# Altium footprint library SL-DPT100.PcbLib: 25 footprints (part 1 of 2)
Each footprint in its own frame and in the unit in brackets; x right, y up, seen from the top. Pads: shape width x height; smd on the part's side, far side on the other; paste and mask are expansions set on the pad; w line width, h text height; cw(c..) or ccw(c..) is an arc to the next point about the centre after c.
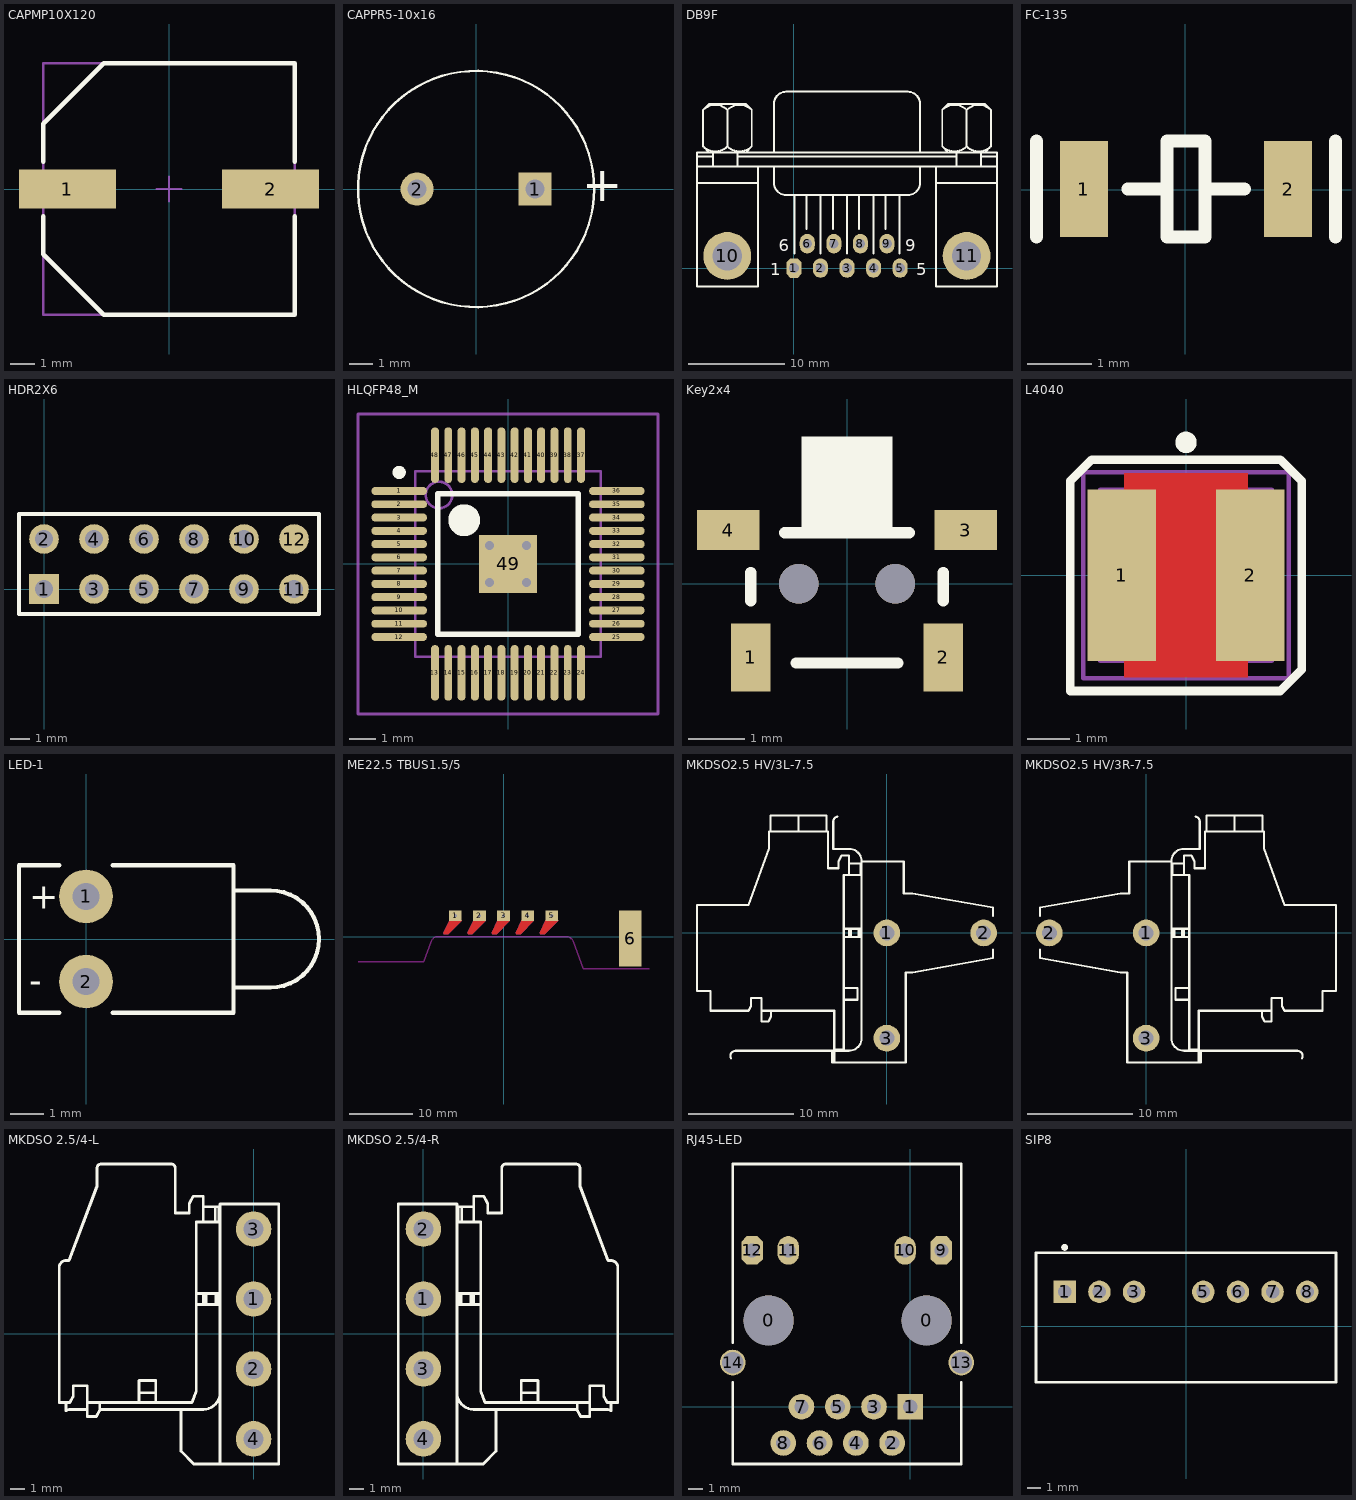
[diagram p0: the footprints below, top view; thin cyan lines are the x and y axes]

## CAPMP10X120 [mm] "Molded Capacitor, 2-Leads, Body 10mmx12mm, IPC High Density"
height 12
pads (2):
  rect 4x1.6 smd: 1(-4.2,0) 2(4.2,0)
Top Overlay:
  lines w0.2: -5.2,-1.125 -5.2,-2.7 -2.7,-5.2 5.2,-5.2 5.2,-1.125 ; -5.2,1.125 -5.2,2.7 -2.7,5.2 5.2,5.2 5.2,1.125
Mechanical 13:
  lines w0.1: -5.2,-2.7 -2.7,-5.2 5.2,-5.2 5.2,5.2 -2.7,5.2 -5.2,2.7 -5.2,-2.7
Mechanical 15:
  lines w0.1: -0.5,0 0.5,0 ; 0,-0.5 0,0.5 ; -5.2,-5.2 5.2,-5.2 5.2,5.2 -5.2,5.2 -5.2,-5.2
3D body: height 12.1, standoff 0.1, extent -4.98,-5 4.98,4.98

## CAPPR5-10x16 [mm] "Capacitor, Electrolytic, Radial; Body 10 x 16 mm (Dia.xH typ); Pin Spacing 5 mm (typ)"
height 10
pads (2):
  rect 1.4x1.4 hole 0.8: 1(2.5,0)
  round 1.4 hole 0.8: 2(-2.5,0)
Top Overlay:
  circle w0.1: c0,0 r5
  text "+" at 6.2,0.75 h1.5

## DB9F [mil]
height 62.99
pads (11):
  oct 62x80 hole 40: 1(0,0)
  oval 62x80 hole 40: 2(109.17,0) 3(218.33,0) 4(327.5,0) 5(436.67,0) 6(55,100) 7(164.17,100) 8(273.33,100) 9(382.5,100)
  round 196.67 hole 120: 10(-274.17,50) 11(710,50)
Top Overlay:
  lines w8: -398.33,350 -148.33,350 ; -398.33,416.67 835,416.67 ; -398.33,458.33 -331.67,458.33 ; -373.42,499.91 ccw(c-323.33,550) -273.25,499.91 ; -373.42,650.09 cw(c-323.33,600) -273.25,650.09 ; -348.33,475 -373.33,500 -373.33,650 -348.33,675 -198.33,675 -173.33,650 -173.33,500 -198.33,475 ; -331.67,416.67 -331.67,475 ; -273.42,499.91 ccw(c-223.33,550) -173.25,499.91 ; -273.42,650.09 cw(c-223.33,600) -173.25,650.09 ; -273.33,500 -273.33,650 ; -231.67,416.67 -231.67,475 ; -231.67,458.33 668.33,458.33 ; -148.33,416.67 -148.33,-75 -398.33,-75 -398.33,475 835,475 835,-75 585,-75 585,416.67 ; -81.67,416.67 -81.67,350 ccw(c-31.67,350) -31.67,300 468.33,300 ccw(c468.33,350) 518.33,350 518.33,416.67 ; -81.67,475 -81.67,675 cw(c-31.67,675) -31.67,725 468.33,725 cw(c468.33,675) 518.33,675 518.33,475 ; 1.67,60.4 1.67,300 ; 51.67,160 51.67,300 ; 110,60.4 110,300 ; 160,160.4 160,300 ; 218.33,60.4 218.33,300 ; 268.33,160 268.33,300 ; 326.67,60.4 326.67,300 ; 376.67,160 376.67,300 ; 435,60.4 435,300 ; 585,350 835,350 ; 609.91,499.91 ccw(c660,550) 710.09,499.91 ; 609.91,650.09 cw(c660,600) 710.09,650.09 ; 635,475 610,500 610,650 635,675 785,675 810,650 810,500 785,475 ; 668.33,416.67 668.33,475 ; 709.91,499.91 ccw(c760,550) 810.09,499.91 ; 709.91,650.09 cw(c760,600) 810.09,650.09 ; 710,500 710,650 ; 768.33,416.67 768.33,475 ; 768.33,458.33 835,458.33
  text "6" at -61.67,70 h50
  text "1" at -96.67,-30 h50
  text "5" at 503.33,-30 h50
  text "9" at 458.33,70 h50

## FC-135 [mm]
height 1.2
pads (2):
  rect 0.75x1.5 smd: 1(-1.587,0.011) 2(1.613,0.011)
Top Overlay:
  lines w0.203: -2.329,-0.739 -2.329,0.761 ; -0.9,0.011 -0.287,0.011 ; 0.413,0.011 0.93,0.011 ; 2.355,-0.739 2.355,0.761 ; -0.287,-0.739 -0.287,0.761 0.313,0.761 0.313,-0.739 -0.287,-0.739

## HDR2X6 [mm] "Connector; Header; 6x2 Position"
height 1.75
pads (12):
  rect 1.5x1.5 hole 0.9: 1(0,0)
  round 1.5 hole 0.9: 2(0,2.54) 3(2.54,0) 4(2.54,2.54) 5(5.08,0) 6(5.08,2.54) 7(7.62,0) 8(7.62,2.54) 9(10.16,0) 10(10.16,2.54) 11(12.7,0)
  round 1.5 smd: 12(12.7,2.54)
Top Overlay:
  lines w0.2: -1.27,-1.27 -1.27,3.81 13.97,3.81 13.97,-1.27 -1.27,-1.27

## HLQFP48_M [mm] "48-Pin Thin Quad Flat Pack 0.5 mm Pitch, IPC Low Density"
height 1.6
pads (49):
  oval 2.1x0.3 smd: 1(-4.1,2.75) 2(-4.1,2.25) 3(-4.1,1.75) 4(-4.1,1.25) 5(-4.1,0.75) 6(-4.1,0.25) 7(-4.1,-0.25) 8(-4.1,-0.75) 9(-4.1,-1.25) 10(-4.1,-1.75) 11(-4.1,-2.25) 12(-4.1,-2.75) 25(4.1,-2.75) 26(4.1,-2.25) 27(4.1,-1.75) 28(4.1,-1.25) 29(4.1,-0.75) 30(4.1,-0.25) 31(4.1,0.25) 32(4.1,0.75) 33(4.1,1.25) 34(4.1,1.75) 35(4.1,2.25) 36(4.1,2.75)
  oval 0.3x2.1 smd: 13(-2.75,-4.1) 14(-2.25,-4.1) 15(-1.75,-4.1) 16(-1.25,-4.1) 17(-0.75,-4.1) 18(-0.25,-4.1) 19(0.25,-4.1) 20(0.75,-4.1) 21(1.25,-4.1) 22(1.75,-4.1) 23(2.25,-4.1) 24(2.75,-4.1) 37(2.75,4.1) 38(2.25,4.1) 39(1.75,4.1) 40(1.25,4.1) 41(0.75,4.1) 42(0.25,4.1) 43(-0.25,4.1) 44(-0.75,4.1) 45(-1.25,4.1) 46(-1.75,4.1) 47(-2.25,4.1) 48(-2.75,4.1)
  rect 2.2x2.2 smd: 49(0,0)
via -0.7,0.7 diameter 0.66 hole 0.33
via 0.7,0.7 diameter 0.66 hole 0.33
via 0.7,-0.7 diameter 0.66 hole 0.33
via -0.7,-0.7 diameter 0.66 hole 0.33
Top Overlay:
  circle w0.25: c-4.1,3.45 r0.125
  circle w0.6: c-1.65,1.65 r0.3
  lines w0.2: -2.65,-2.65 -2.65,2.65 2.65,2.65 2.65,-2.65 -2.65,-2.65
Mechanical 13:
  circle w0.1: c-2.6,2.6 r0.5
  lines w0.1: -3.5,-3.5 -3.5,3.5 3.5,3.5 3.5,-3.5 -3.5,-3.5
Mechanical 15:
  lines w0.1: -0.5,0 0.5,0 ; 0,-0.5 0,0.5 ; -5.65,-5.65 -5.65,5.65 5.65,5.65 5.65,-5.65 -5.65,-5.65
3D body: height 1.6, standoff 0, extent -3.5,-3.5 3.5,3.5

## Key2x4 [mm]
height 1.8
pads (4):
  rect 0.7x1.2 smd: 1(-1.7,-1.3) 2(1.7,-1.3)
  rect 1.1x0.7 smd: 3(2.1,0.95) 4(-2.1,0.95)
via 0.85,0 diameter 0.7 hole 0.7
via -0.85,0 diameter 0.7 hole 0.7
Top Overlay:
  rectangle: -0.8,0.9 0.8,2.6
  lines w0.2: -1.7,-0.3 -1.7,0.2 ; -1.1,0.9 1.1,0.9 ; -0.9,-1.4 0.9,-1.4 ; 1.7,-0.3 1.7,0.2

## L4040 [mm] "Chip Inductor, Body 4.0x4.0mm, IPC Medium Density"
height 3
pads (2):
  rect 1.6x4 smd: 1(-1.5,0) 2(1.5,0)
Top Layer:
  pour cut-out: -1.438,2.375 1.438,2.375 1.438,-2.375 -1.438,-2.375
Top Overlay:
  circle w0.25: c0,3.1 r0.125
  lines w0.2: -2.7,-2.7 2.2,-2.7 2.7,-2.2 2.7,2.2 2.2,2.7 -2.2,2.7 -2.7,2.2 -2.7,-2.7
Mechanical 13:
  lines w0.1: -2,-2 2,-2 2,2 -2,2 -2,-2
Mechanical 15:
  lines w0.1: -0.5,0 0.5,0 ; 0,-0.5 0,0.5 ; -2.4,-2.4 -2.4,2.4 2.4,2.4 2.4,-2.4 -2.4,-2.4
3D body: height 0.71, standoff 0, extent -2,-2 2,2

## LED-1 [mm] "Typical RED GaAs LED; 2 Leads"
height 1.75
pads (2):
  round 1.6 hole 0.8: 1(0,1.27) 2(0,-1.27)
Top Overlay:
  lines w0.127: -0.8,-2.2 -2,-2.2 -2,2.2 -0.8,2.2 ; 0.8,-2.2 4.4,-2.2 4.4,2.2 0.8,2.2 ; 4.4,-1.45 5.5,-1.45 ccw(c5.5,0) 5.5,1.45 4.4,1.45
  text "+" at -1.7,0.9 h0.76
  text "-" at -1.7,-1.6 h0.76

## ME22.5 TBUS1.5/5 [mm]
pads (6):
  rect 2x1.6 hole 0.5: 1(-7.62,3.3) 2(-3.81,3.3) 3(0,3.3) 4(3.8,3.3) 5(7.6,3.3)
  rect 3.6x8.8 hole 0.5: 6(20,-0.3)
Top Layer:
  region: -6.62,2.6 -6.62,2.5 -8.72,0.4 -9.42,0.4 -9.52,0.6 -8.62,2.5 -8.62,2.6
  region: -2.81,2.6 -2.81,2.5 -4.91,0.4 -5.61,0.4 -5.71,0.6 -4.81,2.5 -4.81,2.6
  region: 8.6,2.6 8.6,2.5 6.5,0.4 5.8,0.4 5.7,0.6 6.6,2.5 6.6,2.6
  region: 4.8,2.6 4.8,2.5 2.7,0.4 2,0.4 1.9,0.6 2.8,2.5 2.8,2.6
  region: 1,2.6 1,2.5 -1.1,0.4 -1.8,0.4 -1.9,0.6 -1,2.5 -1,2.6
Bottom Layer:
  region: -6.62,2.6 -6.62,2.5 -8.72,0.4 -9.42,0.4 -9.52,0.6 -8.62,2.5 -8.62,2.6
  region: -2.81,2.6 -2.81,2.5 -4.91,0.4 -5.61,0.4 -5.71,0.6 -4.81,2.5 -4.81,2.6
  region: 8.6,2.6 8.6,2.5 6.5,0.4 5.8,0.4 5.7,0.6 6.6,2.5 6.6,2.6
  region: 4.8,2.6 4.8,2.5 2.7,0.4 2,0.4 1.9,0.6 2.8,2.5 2.8,2.6
  region: 1,2.6 1,2.5 -1.1,0.4 -1.8,0.4 -1.9,0.6 -1,2.5 -1,2.6
Top Solder:
  region: -6.52,2.6 -6.52,2.4 -8.62,0.3 -9.52,0.3 -9.62,0.6 -8.72,2.6
  region: -2.71,2.6 -2.71,2.4 -4.81,0.3 -5.71,0.3 -5.81,0.6 -4.91,2.6
  region: 8.7,2.6 8.7,2.4 6.6,0.3 5.7,0.3 5.6,0.6 6.5,2.6
  region: 4.9,2.6 4.9,2.4 2.8,0.3 1.9,0.3 1.8,0.6 2.7,2.6
  region: 1.1,2.6 1.1,2.4 -1,0.3 -1.9,0.3 -2,0.6 -1.1,2.6
Bottom Solder:
  region: -6.52,2.6 -6.52,2.4 -8.62,0.3 -9.52,0.3 -9.62,0.6 -8.72,2.6
  region: -2.71,2.6 -2.71,2.4 -4.81,0.3 -5.71,0.3 -5.81,0.6 -4.91,2.6
  region: 8.7,2.6 8.7,2.4 6.6,0.3 5.7,0.3 5.6,0.6 6.5,2.6
  region: 4.9,2.6 4.9,2.4 2.8,0.3 1.9,0.3 1.8,0.6 2.7,2.6
  region: 1.1,2.6 1.1,2.4 -1,0.3 -1.9,0.3 -2,0.6 -1.1,2.6
Keep-Out Layer:
  lines w0.2: -23,-3.95 -12.619,-3.95 -11.447,-0.729 ; -11.444,-0.73 cw(c-10.34,-1.2) -10.34,0 9.898,0 ; 9.898,0.002 cw(c9.898,-1.198) 11.002,-0.728 12.6,-5.05 23,-5.05

## MKDSO2.5 HV/3L-7.5 [mil]
pads (3):
  round 100 hole 56: 1(0,0) 2(362.2,0) 3(0.04,-393.74)
Top Overlay:
  lines w7.87: -584.02,-468.89 cw(c-566.15,-460.63) -566.15,-440.95 -141.73,-440.95 ccw(c-141.73,-393.7) -94.49,-393.7 -94.49,267.72 ccw(c-141.73,267.72) -141.73,314.96 -200.79,314.96 -200.79,416.26 cw(c-181.1,416.26) -184.41,435.66 ; -330.71,379.92 -330.71,438.98 ; -196.85,-440.95 -196.85,-437.01 ; -196.64,-482.99 -196.64,-436.98 ; -196.64,-440.92 -204.51,-440.92 -204.51,-484.23 70.87,-484.23 70.87,-147.61 96.42,-147.61 397.85,-94.46 397.85,-62.99 ; -94.49,259.84 -98.42,259.84 ; -94.28,259.87 -94.28,267.74 63.2,267.74 63.2,147.66 96.42,147.66 397.85,94.51 397.85,62.99 ; -468.5,-291.34 -468.5,-330.71 -442.91,-330.71 -433.07,-313.66 -433.07,-291.34 ; -468.5,-291.34 -468.5,-244.09 -507.87,-244.1 -507.87,-274.29 -517.71,-291.34 -659.45,-291.34 -659.45,-216.54 -710.63,-216.54 -710.63,104.33 -518.32,104.33 -440.94,316.93 -440.94,379.92 -435.04,379.92 ; -468.5,-291.34 -433.07,-291.34 ; -435.04,379.92 -226.38,379.92 ; -435.04,379.92 -435.04,438.98 -226.38,438.98 -226.38,379.92 ; -433.07,-291.34 -196.85,-291.34 -196.85,-437.01 ; -226.38,379.92 -220.47,379.92 -220.47,242.13 -181.1,242.13 -181.1,268.91 -169.29,289.37 -141.73,289.37 -141.73,259.84 ; -196.85,-437.01 -161.41,-437.01 -161.41,-250 ; -161.41,-250 -161.41,-206.69 ; -161.41,-250 -110.23,-250 -110.23,-206.69 -161.41,-206.69 ; -161.41,-206.69 -161.41,-15.75 ; -161.41,-15.75 -141.73,-15.75 ; -161.41,-15.75 -161.41,15.75 ; -161.41,15.75 -161.41,216.54 -141.73,216.53 ; -161.41,15.75 -141.73,15.75 ; -141.73,-15.75 -141.73,15.75 ; -141.73,-15.75 -133.86,-15.75 ; -141.73,15.75 -133.86,15.75 ; -141.73,216.53 -141.73,259.84 ; -141.73,216.53 -98.42,216.54 -98.42,259.84 ; -141.73,259.84 -98.42,259.84 ; -133.86,-15.75 -106.3,-15.75 ; -133.86,-15.75 -133.86,15.75 ; -133.86,15.75 -106.3,15.75 ; -106.3,-15.75 -106.3,15.75 ; -106.3,-15.75 -98.42,-15.75 -98.42,15.75 -106.3,15.75

## MKDSO2.5 HV/3R-7.5 [mil]
pads (3):
  round 100 hole 56: 1(0,0) 2(-362.2,0) 3(-0.04,-393.74)
Top Overlay:
  lines w7.87: -397.85,-62.99 -397.85,-94.46 -96.42,-147.61 -70.87,-147.61 -70.87,-484.23 204.51,-484.23 204.51,-440.92 196.64,-440.92 ; -397.85,62.99 -397.85,94.51 -96.42,147.66 -63.21,147.66 -63.21,267.74 94.28,267.74 94.28,259.87 ; 94.49,259.84 98.42,259.84 ; 184.41,435.66 cw(c181.1,416.26) 200.79,416.26 200.79,314.96 141.73,314.96 ccw(c141.73,267.72) 94.49,267.72 94.49,-393.7 ccw(c141.73,-393.7) 141.73,-440.95 566.15,-440.95 cw(c566.15,-460.63) 584.02,-468.89 ; 196.64,-482.99 196.64,-436.98 ; 196.85,-440.95 196.85,-437.01 ; 330.71,379.92 330.71,438.98 ; 98.42,259.84 141.73,259.84 ; 98.42,259.84 98.42,216.54 141.73,216.53 ; 106.3,-15.75 98.42,-15.75 98.42,15.75 106.3,15.75 ; 106.3,-15.75 133.86,-15.75 ; 106.3,-15.75 106.3,15.75 ; 106.3,15.75 133.86,15.75 ; 133.86,-15.75 141.73,-15.75 ; 133.86,-15.75 133.86,15.75 ; 133.86,15.75 141.73,15.75 ; 141.73,-15.75 141.73,15.75 ; 141.73,-15.75 161.41,-15.75 ; 141.73,15.75 161.41,15.75 ; 141.73,216.53 161.41,216.54 161.41,15.75 ; 141.73,216.53 141.73,259.84 ; 141.73,259.84 141.73,289.37 169.29,289.37 181.1,268.91 181.1,242.13 220.47,242.13 220.47,379.92 226.38,379.92 ; 161.41,-250 161.41,-437.01 196.85,-437.01 ; 161.41,-250 110.23,-250 110.23,-206.69 161.41,-206.69 ; 161.41,-250 161.41,-206.69 ; 161.41,-206.69 161.41,-15.75 ; 161.41,-15.75 161.41,15.75 ; 196.85,-437.01 196.85,-291.34 433.07,-291.34 ; 226.38,379.92 226.38,438.98 435.04,438.98 435.04,379.92 ; 226.38,379.92 435.04,379.92 ; 433.07,-291.34 468.5,-291.34 ; 433.07,-291.34 433.07,-313.66 442.91,-330.71 468.5,-330.71 468.5,-291.34 ; 435.04,379.92 440.94,379.92 440.94,316.93 518.32,104.33 710.63,104.33 710.63,-216.54 659.45,-216.54 659.45,-291.34 517.71,-291.34 507.87,-274.29 507.87,-244.1 468.5,-244.09 468.5,-291.34

## MKDSO 2.5/4-L [mm]
height 12.75
pads (4):
  round 2.54 hole 1.422: 1(0,2.5) 2(0,-2.5) 3(0,7.5) 4(0,-7.5)
Top Overlay:
  lines w0.2: -13.406,-4.993 -13.406,-5.488 cw(c-13.122,-5.899) -13.122,-5.399 -11.9,-5.399 ; -11,-5.399 -5.2,-5.399 ; -5,-5.399 -5.2,-5.399 ; -4.1,2.1 -3.6,2.1 ; -4.1,2.9 -3.6,2.9 ; -2.4,-9.299 -2.4,9.3 ; -2.4,-4.2 cw(c-3.6,-4.2) -3.6,-5.4 -5.199,-5.4 ; -2.4,2.1 -2.5,2.1 ; -2.4,2.9 -2.5,2.9 ; -2.4,9.101 -2.4,9.301 ; -11.9,-4.899 -11.9,-5.899 -11.25,-5.899 -11,-5.466 -11,-4.899 ; -11.9,-4.899 -11.9,-3.699 -12.9,-3.699 -12.9,-4.466 -13.15,-4.899 -13.9,-4.899 -13.9,4.751 cw(c-13.4,4.751) -13.4,5.251 -13.2,5.251 -11.2,10.551 -11.2,11.851 cw(c-10.9,11.851) -10.9,12.151 -5.9,12.151 cw(c-5.9,11.851) -5.6,11.851 -5.6,8.651 -4.6,8.651 -4.6,9.331 -4.3,9.851 -3.6,9.851 -3.6,9.101 ; -11.9,-4.899 -11,-4.899 ; -11,-4.899 -8.2,-4.899 ; -8.2,-4.899 -8.2,-4.199 ; -8.2,-4.899 -7,-4.899 ; -8.2,-4.199 -8.2,-3.333 -7,-3.333 -7,-4.199 ; -8.2,-4.199 -7,-4.199 ; -7,-4.899 -7,-4.199 ; -7,-4.899 -5,-4.899 -4.4,-4.899 -4.1,-4.099 -4.1,2.832 -4.1,8.001 -3.6,8.001 ; -5.2,-5.399 -5.2,-8.382 -4.283,-9.299 1.8,-9.299 1.8,9.301 -2.4,9.301 ; -3.6,8.001 -3.6,9.101 ; -3.6,8.001 -2.75,8.001 ; -3.6,9.101 -2.75,9.101 ; -3.6,2.1 -3.6,2.9 ; -3.6,2.1 -3.4,2.1 ; -3.6,2.9 -3.4,2.9 ; -3.4,2.1 -3.4,2.9 ; -3.4,2.1 -2.7,2.1 ; -3.4,2.9 -2.7,2.9 ; -2.75,8.001 -2.75,9.101 ; -2.75,8.001 -2.5,8.001 -2.5,9.101 -2.75,9.101 ; -2.7,2.1 -2.7,2.9 ; -2.7,2.1 -2.5,2.1 ; -2.7,2.9 -2.5,2.9 ; -2.5,2.1 -2.5,2.9

## MKDSO 2.5/4-R [mm]
pads (4):
  round 2.54 hole 1.422: 1(0,2.5) 2(0,7.5) 3(0,-2.5) 4(0,-7.5)
Top Overlay:
  lines w0.2: 2.4,-9.299 2.4,9.3 ; 2.4,-4.2 ccw(c3.6,-4.2) 3.6,-5.4 5.2,-5.4 ; 2.4,2.1 2.5,2.1 ; 2.4,2.9 2.5,2.9 ; 2.4,9.101 2.4,9.301 ; 4.1,2.1 3.6,2.1 ; 4.1,2.9 3.6,2.9 ; 5,-5.399 5.2,-5.399 ; 11,-5.399 5.2,-5.399 ; 11.9,-5.399 13.123,-5.399 cw(c13.123,-5.899) 13.407,-5.488 13.407,-4.993 ; 2.4,9.301 -1.8,9.301 -1.8,-9.299 4.283,-9.299 5.2,-8.382 5.2,-5.399 ; 2.5,2.1 2.5,2.9 ; 2.5,2.1 2.7,2.1 ; 2.5,2.9 2.7,2.9 ; 2.7,2.1 2.7,2.9 ; 2.7,2.1 3.4,2.1 ; 2.7,2.9 3.4,2.9 ; 2.75,8.001 2.75,9.101 ; 2.75,8.001 2.5,8.001 2.5,9.101 2.75,9.101 ; 2.75,8.001 3.6,8.001 ; 2.75,9.101 3.6,9.101 ; 3.4,2.1 3.6,2.1 ; 3.4,2.1 3.4,2.9 ; 3.4,2.9 3.6,2.9 ; 3.6,2.1 3.6,2.9 ; 3.6,8.001 3.6,9.101 ; 3.6,8.001 4.1,8.001 4.1,2.832 4.1,-4.099 4.4,-4.899 5,-4.899 7,-4.899 ; 3.6,9.101 3.6,9.851 4.3,9.851 4.6,9.331 4.6,8.651 5.6,8.651 5.6,11.851 cw(c5.9,11.851) 5.9,12.151 10.9,12.151 cw(c10.9,11.851) 11.2,11.851 11.2,10.551 13.2,5.251 13.4,5.251 cw(c13.4,4.751) 13.9,4.751 13.9,-4.899 13.15,-4.899 12.9,-4.466 12.9,-3.699 11.9,-3.699 11.9,-4.899 ; 7,-4.899 7,-4.199 ; 7,-4.899 8.2,-4.899 ; 7,-4.199 7,-3.333 8.2,-3.333 8.2,-4.199 ; 7,-4.199 8.2,-4.199 ; 8.2,-4.899 11,-4.899 ; 8.2,-4.899 8.2,-4.199 ; 11,-4.899 11,-5.466 11.25,-5.899 11.9,-5.899 11.9,-4.899 ; 11,-4.899 11.9,-4.899

## RJ45-LED [mm]
height 4.83
pads (16):
  round 3.5 hole 3.5: 0(-9.9,6.035) 0(1.16,6.035)
  rect 1.8x1.8 hole 1: 1(0.01,-0.005)
  round 1.8 hole 1: 2(-1.26,-2.545) 3(-2.53,-0.005) 4(-3.8,-2.545) 5(-5.07,-0.005) 6(-6.34,-2.545) 7(-7.61,-0.005) 8(-8.88,-2.545)
  oct 1.5x2 hole 0.991: 9(2.185,10.935) 12(-11.065,10.935)
  oval 1.5x2 hole 0.991: 10(-0.355,10.935) 11(-8.525,10.935)
  round 1.8 hole 1.5: 13(3.58,3.085) 14(-12.42,3.085)
Top Overlay:
  lines w0.2: -12.42,1.68 -12.42,-4.015 3.58,-4.015 3.58,1.68 ; -12.42,4.5 -12.42,16.985 3.58,16.985 3.58,4.5

## SIP8 [mm] "SIP; 8 Round Pins; Body 22x9.5mm; Pitch 2.54 mm"
height 12
pads (7):
  rect 1.65x1.65 hole 1: 1(-8.89,2.54)
  round 1.65 hole 1: 2(-6.35,2.54) 3(-3.81,2.54) 5(1.27,2.54) 6(3.81,2.54) 7(6.35,2.54) 8(8.89,2.54)
Top Overlay:
  circle w0.25: c-8.9,5.8 r0.125
  lines w0.2: -11,-4.1 -11,5.4 11,5.4 11,-4.1 -11,-4.1
Mechanical 13:
  lines w0.1: -11,-4.1 11,-4.1 11,5.4 -11,5.4 -11,-4.1
3D body: height 12, standoff 0, extent -11,-4.1 11,5.4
